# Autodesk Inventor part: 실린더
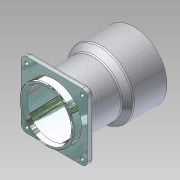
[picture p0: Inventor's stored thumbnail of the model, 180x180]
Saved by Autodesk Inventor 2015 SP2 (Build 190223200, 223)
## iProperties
Manager: KYOUNG IL JANG
Company: 한국ATC센터
Created: 2012-10
Part Number: 실린더
Material: 일반
Document SubType Name: 모델링
Density: 1 g/cm^3
Checked By: KYOUNG IL JANG
Vendor: CBT Solutions
Designer: KYOUNG IL JANG
Sheet Metal Rule: 기본값_mm
Appearance: _시험_알루미늄 표면거칠기
Author: KYOUNG IL JANG
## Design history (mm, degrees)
sketch "스케치1"
  geometry: L1 (0, 0)-(0, 112); L2 (30, 0)-(30, 112); L3 (30, 112)-(42.5, 112); L4 (42.5, 112)-(42.5, 69); L5 (42.5, 69)-(35, 61); L6 (35, 61)-(35, 0); L7 (35, 0)-(30, 0)
  constraints: 14 end point, 4 parallel, 2 point on line, 1 perpendicular, 1 vertical
  dimensions: "d0" = 112 distance of L1.start L1.end; "d2" = 85 diameter of L4 L1; "d3" = 70 diameter of L6 L1; "d5" = 60 diameter of L2 L1; "d33" = 43 distance of L3.end L4.end; "d34" = 51 distance from line of L3 L5.end
revolve "회전1" stored, may be unused: angle "d6" = 90 deg
node "작업 평면1"
sketch "스케치2"
  geometry: L1 (-42.5, 42.5)-(42.5, 42.5); L2 (42.5, 42.5)-(42.5, -42.5); L3 (42.5, -42.5)-(-42.5, -42.5); L4 (-42.5, -42.5)-(-42.5, 42.5); C1 r 35 at (0, 0) reference; 3 further points
  constraints: 8 end point, 2 midpoint, 2 parallel, 2 perpendicular, 1 horizontal, 1 horizontal alignment, 1 vertical alignment
  dimensions: "d8" = 85 distance of L1.end L2.end
extrude "돌출1" join sketch "스케치2" distance "d9" = 8; taper "d10" = 0 deg
fillet "모깎기1" dims "d11" = 7, "d12" = 3
sketch "스케치3"
  geometry: L1 (0, 42.5)-(0, 30); 4 further points
  constraints: 2 end point, 2 vertical alignment, 1 midpoint, 1 point on line, 1 vertical, 2 other
hole "구멍1" sketch "스케치3" at (0, 36.25) diameter "d14" = 4.134; stored, may be unused: countersink angle "d18" = 90 deg, drill point angle "d20" = 118 deg; dims "d15" = 12, "d16" = 4, "d17" = 2, "d19" = 15
sketch "스케치4"
  geometry: C1 r 1.621 at (35.5, -35.5) reference; C2 r 1.621 at (35.5, 35.5) reference; C3 r 1.621 at (-35.5, -35.5) reference; C4 r 1.621 at (-35.5, 35.5) reference; 1 further point
hole "구멍2" sketch "스케치4" at (35.5, 35.5), (35.5, -35.5), (-35.5, -35.5), (-35.5, 35.5) diameter "d26" = 4.5; stored, may be unused: countersink angle "d30" = 90 deg, drill point angle "d32" = 118 deg; dims "d27" = 12, "d28" = 8, "d29" = 4.4, "d31" = 15
chamfer "모따기1" distance "d35" = 5; stored, may be unused: second distance "d36" = 2, angle "d37" = 20 deg
chamfer "모따기2" distance "d38" = 1; stored, may be unused: second distance "d39" = 2, angle "d40" = 20 deg
node "솔리드1"
pattern_circular "원형 패턴1" dims angle "d22" = 360 deg
node "참조1"
node "참조2"
node "참조3"
node "참조4"
other parameters: "KFactor" = 4.4
